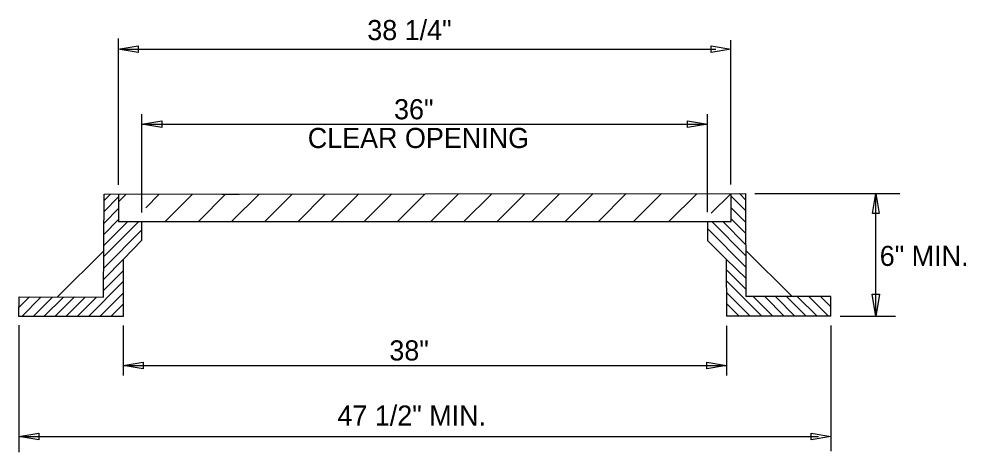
# Model space of a CAD drawing. Extents: x 0 to 31.8, y -0.5 to 20.8.
# Drawn here: x 13.45 to 18.64, y 5.64 to 8.01 of the extents above; entities that cross this region are included whole.
import ezdxf

# ---------------------------------------------------------------- set-up
doc = ezdxf.new("R2010")
doc.units = 0
for name, color, linetype in [('CT_Dimensions', 7, 'Continuous'), ('sb_Dimension Lines', 7, 'Continuous'), ('sb_Existing Structural Steel', 7, 'Continuous')]:
    doc.layers.add(name, color=color, linetype=linetype)

# ---------------------------------------------------------------- blocks, each defined once
blk = doc.blocks.new('Dimension Terminator')
at = {"layer": 'sb_Dimension Lines'}
blk.add_lwpolyline([(-0.119, 0.0198), (0, 0), (-0.119, -0.0198)], close=True, dxfattribs=at)

msp = doc.modelspace()

# ---------------------------------------------------------------- linework, layer by layer
at = {"layer": 'CT_Dimensions'}
for p, q in [((13.995, 7.105), (13.995, 7.9056)), ((17.3487, 7.1071), (17.3487, 7.8973)), ((14.0162, 7.8475), (17.2654, 7.8473)), ((14.1238, 6.9532), (14.1238, 7.4912)), ((17.22, 6.9545), (17.22, 7.4912)), ((14.1238, 7.4362), (17.22, 7.4362)), ((17.4787, 7.0566), (18.273, 7.0566)), ((18.1412, 6.3854), (18.1412, 7.0561)), ((17.947, 6.3854), (18.2495, 6.3854)), ((13.4507, 6.3359), (13.4507, 5.6412)), ((14.0213, 6.3346), (14.0213, 6.0604)), ((17.3251, 6.3327), (17.3251, 6.0604)), ((17.8962, 6.3339), (17.8962, 5.6456)), ((14.0213, 6.1154), (17.3251, 6.1154)), ((13.4507, 5.7256), (17.8276, 5.7256))]:
    msp.add_line(p, q, dxfattribs=at)
for points in [[(14.1304, 6.0973), (14.0213, 6.1154), (14.1304, 6.1336)], [(17.216, 6.1336), (17.3251, 6.1154), (17.216, 6.0973)]]:
    msp.add_lwpolyline(points, close=True, dxfattribs=at)
at = {"layer": 'sb_Existing Structural Steel'}
for p, q in [((13.9145, 6.49), (13.9168, 7.0536)), ((13.9165, 7.0186), (13.9513, 7.0535)), ((13.9168, 7.0536), (17.4299, 7.0564)), ((13.9955, 7.0537), (13.9961, 6.9046)), ((14.1449, 6.9793), (14.2189, 7.0537)), ((14.4357, 6.9057), (14.5811, 7.0537)), ((14.5612, 7.0537), (14.6563, 7.0537)), ((14.979, 6.904), (15.1266, 7.054)), ((15.3429, 6.9049), (15.4929, 7.0548)), ((17.3499, 6.9037), (17.3499, 7.0565)), ((17.4302, 7.0214), (17.3954, 7.0563)), ((17.4322, 6.4929), (17.4299, 7.0564)), ((13.9168, 6.9592), (13.9956, 7.0383)), ((17.4299, 6.962), (17.35, 7.0424)), ((13.9164, 6.8954), (13.996, 6.9753)), ((17.4303, 6.8982), (17.35, 6.9788)), ((13.9153, 6.8333), (13.9959, 6.9142)), ((13.9153, 6.7724), (14.047, 6.9046)), ((13.9153, 6.712), (14.1071, 6.9045)), ((13.9961, 6.9046), (17.3499, 6.9037)), ((14.1233, 6.801), (14.1238, 6.9044)), ((17.22, 6.904), (17.2203, 6.8006)), ((17.4314, 6.7148), (17.2432, 6.9038)), ((17.4308, 6.7758), (17.304, 6.9032)), ((17.4304, 6.8372), (17.35, 6.9179)), ((13.9148, 6.649), (14.123, 6.8581)), ((17.4319, 6.6519), (17.22, 6.8647)), ((14.0213, 6.6957), (14.1233, 6.801)), ((17.2203, 6.8006), (17.3232, 6.6981)), ((13.66, 6.4901), (13.9166, 6.7457)), ((17.6837, 6.4935), (17.431, 6.7441)), ((13.9147, 6.5883), (14.0213, 6.6954)), ((14.0213, 6.6957), (14.0213, 6.3844)), ((17.3232, 6.6981), (17.3251, 6.3849)), ((17.432, 6.5912), (17.3232, 6.6981)), ((17.4315, 6.531), (17.3238, 6.6382)), ((13.9152, 6.5281), (14.0209, 6.6343)), ((13.8306, 6.3839), (14.021, 6.5752)), ((17.5176, 6.3851), (17.324, 6.5795)), ((13.4507, 6.3843), (13.4515, 6.4908)), ((13.4508, 6.433), (13.5082, 6.4904)), ((13.4515, 6.4908), (13.9145, 6.49)), ((13.4665, 6.3842), (13.5714, 6.4896)), ((13.5287, 6.3843), (13.6336, 6.4897)), ((13.589, 6.3847), (13.694, 6.4901)), ((13.6498, 6.3851), (13.7547, 6.4905)), ((13.708, 6.3843), (13.8129, 6.4897)), ((13.7699, 6.3839), (13.8748, 6.4893)), ((13.8955, 6.3856), (14.0209, 6.5115)), ((17.4544, 6.3857), (17.3244, 6.5157)), ((17.8952, 6.4937), (17.4322, 6.4929)), ((17.5779, 6.3854), (17.4699, 6.4929)), ((17.6405, 6.3851), (17.5338, 6.4925)), ((17.6992, 6.3853), (17.592, 6.4933)), ((17.7598, 6.3852), (17.6528, 6.4929)), ((17.8209, 6.3852), (17.7119, 6.4932)), ((17.882, 6.3854), (17.7742, 6.4932)), ((17.8959, 6.4358), (17.8385, 6.4932)), ((17.8962, 6.385), (17.8952, 6.4937)), ((13.9541, 6.3835), (14.0216, 6.4512)), ((17.3937, 6.3853), (17.3249, 6.4546)), ((14.0213, 6.3844), (13.4507, 6.3843)), ((17.8962, 6.385), (17.3251, 6.3849))]:
    msp.add_line(p, q, dxfattribs=at)
for points in [[(14.0002, 7.0159), (14.0381, 7.0537)], [(14.253, 6.9053), (14.4015, 7.0537)], [(14.6168, 6.9056), (14.765, 7.0537)], [(14.796, 6.9031), (14.9467, 7.0537)], [(15.1617, 6.9054), (15.3112, 7.0548)], [(15.5245, 6.9047), (15.6736, 7.0537)], [(15.7057, 6.9042), (15.8553, 7.0537)], [(15.8862, 6.903), (16.037, 7.0537)], [(16.0689, 6.904), (16.221, 7.056)], [(16.2587, 6.9037), (16.4108, 7.0558)], [(16.5046, 6.9671), (16.5944, 7.0568)], [(16.6238, 6.9046), (16.7759, 7.0567)], [(16.8152, 6.9033), (16.9683, 7.0564)], [(17.009, 6.9036), (17.1616, 7.0561)], [(17.2411, 6.9486), (17.3481, 7.0557)], [(16.4423, 6.9047), (16.5161, 6.9785)], [(17.196, 6.9036), (17.1972, 6.9047)]]:
    msp.add_lwpolyline(points, dxfattribs=at)

# ---------------------------------------------------------------- block references
at = {"layer": 'CT_Dimensions'}
for p, xscale, yscale in [((17.22, 7.4362), 0.9164286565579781, 0.916398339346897), ((17.8962, 5.7256), 0.9164286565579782, 0.9163983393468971)]:
    msp.add_blockref('Dimension Terminator', p, dxfattribs=dict(at, xscale=xscale, yscale=yscale))
for p, xscale, yscale, rotation in [((18.1412, 7.0567), 0.9164286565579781, 0.916398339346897, 90), ((18.1415, 6.3838), 1.0279687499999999, 1.02796875, -90.19425815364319), ((13.4507, 5.7256), 0.9164286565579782, 0.9163983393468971, 180)]:
    msp.add_blockref('Dimension Terminator', p, dxfattribs=dict(at, xscale=xscale, yscale=yscale, rotation=rotation))
at = {"layer": 'sb_Dimension Lines', "xscale": 0.9164286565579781, "yscale": 0.916398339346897, "rotation": 180}
for p in [(13.9946, 7.8469), (14.1238, 7.4362)]:
    msp.add_blockref('Dimension Terminator', p, dxfattribs=at)
at = {"layer": 'sb_Dimension Lines', "xscale": 0.9164286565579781, "yscale": 0.916398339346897}
msp.add_blockref('Dimension Terminator', (17.3487, 7.8467), dxfattribs=at)

# ---------------------------------------------------------------- texts
at = {"layer": 'CT_Dimensions'}
for s, p in [('38 1/4" ', (15.3577, 7.897)), ('36" ', (15.5043, 7.4634)), ('CLEAR OPENING', (15.0319, 7.306)), ('6" MIN.', (18.1632, 6.6605)), ('38" ', (15.4785, 6.1427)), ('47 1/2" MIN. ', (15.1942, 5.786))]:
    msp.add_text(s, height=0.11016, dxfattribs=at).set_placement(p)

doc.saveas('drawing.dxf')
